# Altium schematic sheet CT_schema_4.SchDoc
size 293 x 258 mm
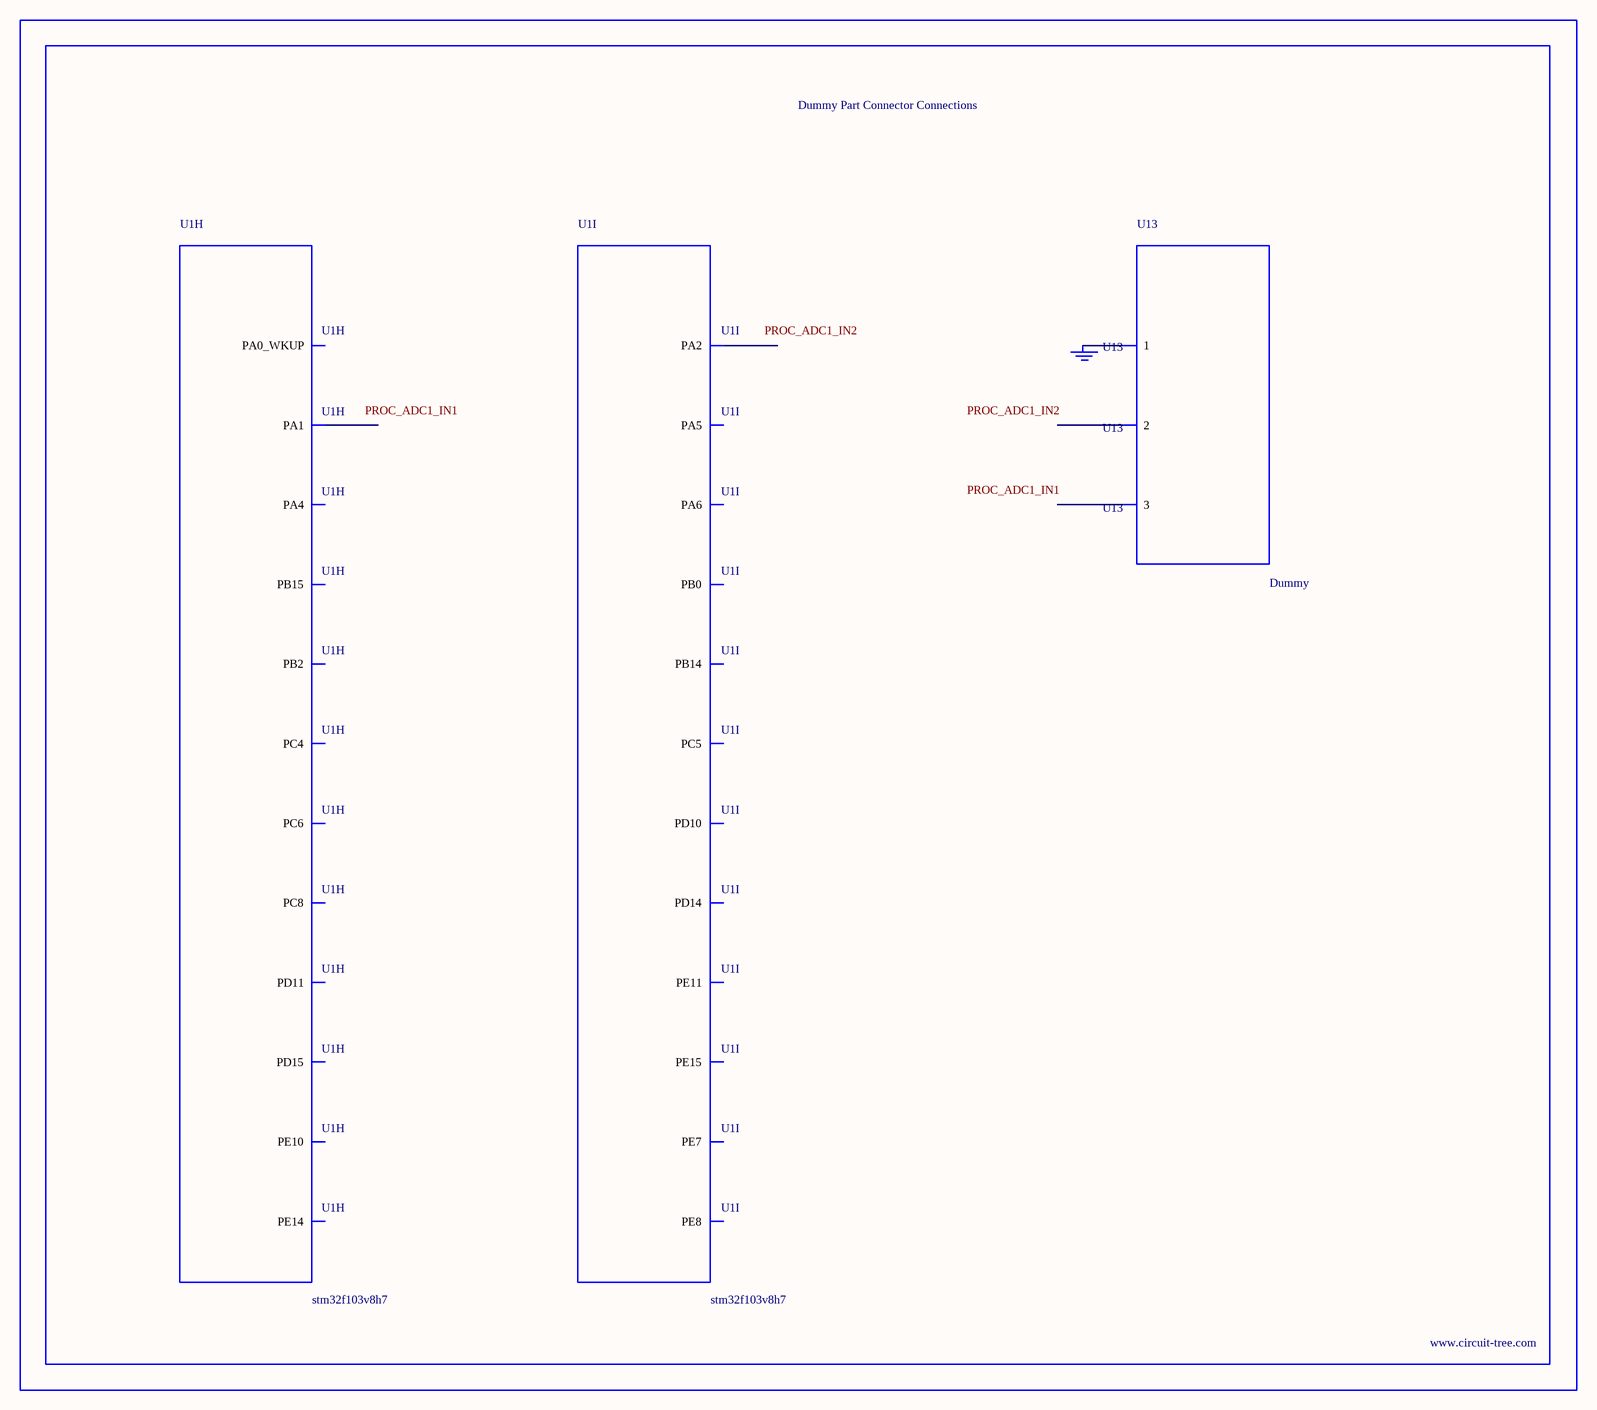
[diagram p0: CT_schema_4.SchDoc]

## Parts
BORDER3  (no value)
GND_INSTANCE_3_0  (no value)
U1  stm32f103v8h7  [LFBGA100]  (parts H,I of 9)
U13  Dummy  [DUMMY_PACKAGE_110]

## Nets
NetGND_INSTANCE_3_0_0: GND_INSTANCE_3_0.0(GND) U13.1

Not connected (* = marked no-connect by the designer): U1 F9(PC8) F10(PC6) G2(PA0_WKUP) G3(PA4) G4(PC4) G5(PB2) G6(PE10) G7(PE14) G8(PB15) G9(PD11) G10(PD15) H2(PA1) H3(PA5) H4(PC5) H5(PE7) H6(PE11) H7(PE15) H8(PB14) H9(PD10) H10(PD14) J2(PA2) J3(PA6) J4(PB0) J5(PE8); U13 2 3

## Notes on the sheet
- Labels drawn without touching a wire or pin: PROC_ADC1_IN1, PROC_ADC1_IN2

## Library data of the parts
BORDER3 = BORDER_PAGE3
GND_INSTANCE_3_0 = GND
